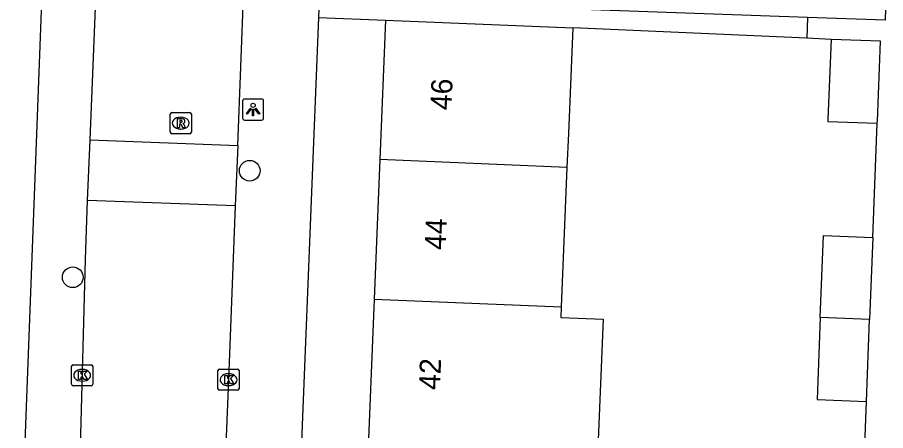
# Model space of a CAD drawing. Extents: x 161355 to 162026, y 386504 to 387459.
# Drawn here: x 161733.14 to 161774.19, y 386889.6 to 386909.14 of the extents above; entities that cross this region are included whole.
import ezdxf

# ---------------------------------------------------------------- set-up
doc = ezdxf.new("R2010")
doc.units = 0
for name, color, linetype in [('IMGEO_Boom', 7, 'Continuous'), ('IMGEO_Kolk', 7, 'Continuous'), ('IMGEO_Lichtpunt', 7, 'Continuous'), ('IMGEO_Pand', 7, 'Continuous'), ('IMGEO_Pand_nummerreeks', 7, 'Continuous'), ('IMGEO_Rijbaan_lokaal_open', 7, 'Continuous'), ('IMGEO_Rioolput', 7, 'Continuous'), ('IMGEO_Voetpad_open', 7, 'Continuous')]:
    doc.layers.add(name, color=color, linetype=linetype)

msp = doc.modelspace()

# ---------------------------------------------------------------- linework, layer by layer
at = {"layer": 'IMGEO_Boom'}
for centre in [(161744.129, 386901.888), (161735.763, 386896.854)]:
    msp.add_circle(centre, 0.489, dxfattribs=at)
at = {"layer": 'IMGEO_Kolk'}
for p, q in [((161735.707, 386891.795), (161735.707, 386892.647)), ((161735.782, 386892.721), (161736.634, 386892.721)), ((161736.195, 386892.501), (161736.22, 386892.501)), ((161736.708, 386892.647), (161736.708, 386891.795)), ((161742.701, 386892.513), (161743.553, 386892.513)), ((161742.626, 386891.587), (161742.626, 386892.439)), ((161743.114, 386892.293), (161743.139, 386892.293)), ((161743.627, 386892.439), (161743.627, 386891.587)), ((161736.634, 386891.721), (161735.782, 386891.721)), ((161736.218, 386891.941), (161736.193, 386891.941)), ((161743.137, 386891.733), (161743.112, 386891.733)), ((161743.553, 386891.513), (161742.701, 386891.513))]:
    msp.add_line(p, q, dxfattribs=at)
for points in [[(161735.707, 386891.795), (161735.707, 386892.647)], [(161735.782, 386892.721), (161736.634, 386892.721)], [(161736.708, 386892.647), (161736.708, 386891.795)], [(161742.701, 386892.513), (161743.553, 386892.513)], [(161736.028, 386892.421), (161736.151, 386892.421), (161736.151, 386892.27), (161736.281, 386892.421), (161736.445, 386892.421), (161736.299, 386892.27), (161736.452, 386892.021), (161736.3, 386892.021), (161736.215, 386892.185), (161736.151, 386892.118), (161736.151, 386892.021), (161736.028, 386892.021), (161736.028, 386892.421)], [(161742.626, 386891.587), (161742.626, 386892.439)], [(161742.947, 386892.213), (161743.07, 386892.213), (161743.07, 386892.062), (161743.2, 386892.213), (161743.364, 386892.213), (161743.218, 386892.062), (161743.371, 386891.813), (161743.219, 386891.813), (161743.134, 386891.977), (161743.07, 386891.91), (161743.07, 386891.813), (161742.947, 386891.813), (161742.947, 386892.213)], [(161743.627, 386892.439), (161743.627, 386891.587)], [(161736.634, 386891.721), (161735.782, 386891.721)], [(161743.553, 386891.513), (161742.701, 386891.513)]]:
    msp.add_lwpolyline(points, dxfattribs=at)
for centre, start, end in [((161735.784, 386892.645), 91.552, 178.448), ((161735.784, 386892.645), 91.552, 178.448), ((161736.632, 386892.645), 1.552, 88.448), ((161736.632, 386892.645), 1.552, 88.448), ((161742.703, 386892.437), 91.552, 178.448), ((161742.703, 386892.437), 91.552, 178.448), ((161743.551, 386892.437), 1.552, 88.448), ((161743.551, 386892.437), 1.552, 88.448), ((161735.784, 386891.797), 181.552, 268.448), ((161735.784, 386891.797), 181.552, 268.448), ((161736.632, 386891.797), 271.552, 358.448), ((161736.632, 386891.797), 271.552, 358.448), ((161742.703, 386891.589), 181.552, 268.448), ((161742.703, 386891.589), 181.552, 268.448), ((161743.551, 386891.589), 271.552, 358.448), ((161743.551, 386891.589), 271.552, 358.448)]:
    msp.add_arc(centre, 0.0765, start, end, dxfattribs=at)
for centre, major_axis, ratio, start_param, end_param in [((161736.194, 386892.221), (-0.387, 0.002), 0.722429, 4.712389, 7.853982), ((161736.219, 386892.221), (-0.39, 0.002), 0.717154, 1.570796, 4.712389), ((161743.113, 386892.013), (-0.387, 0.002), 0.722429, 4.712389, 7.853982), ((161743.138, 386892.013), (-0.39, 0.002), 0.717154, 1.570796, 4.712389)]:
    msp.add_ellipse(centre, major_axis=major_axis, ratio=ratio, start_param=start_param, end_param=end_param, dxfattribs=at)
at = {"layer": 'IMGEO_Lichtpunt'}
for p, q in [((161743.79, 386905.182), (161743.79, 386904.375)), ((161743.79, 386905.182), (161743.79, 386904.375)), ((161744.692, 386905.277), (161743.884, 386905.277)), ((161744.692, 386905.277), (161743.884, 386905.277)), ((161744.786, 386904.375), (161744.786, 386905.182)), ((161744.786, 386904.375), (161744.786, 386905.182)), ((161743.884, 386904.281), (161744.692, 386904.281)), ((161743.884, 386904.281), (161744.692, 386904.281))]:
    msp.add_line(p, q, dxfattribs=at)
for points in [[(161744.164, 386904.846), (161744.203, 386904.818), (161744.015, 386904.556), (161743.977, 386904.583), (161744.164, 386904.846)], [(161744.266, 386904.798), (161744.313, 386904.798), (161744.313, 386904.476), (161744.266, 386904.476), (161744.266, 386904.798)], [(161744.376, 386904.818), (161744.414, 386904.845), (161744.601, 386904.583), (161744.562, 386904.555), (161744.376, 386904.818)]]:
    msp.add_lwpolyline(points, dxfattribs=at)
msp.add_circle((161744.289, 386904.98), 0.0994, dxfattribs=at)
for centre, start, end in [((161743.884, 386905.182), 90, 180), ((161743.884, 386905.182), 90, 180), ((161744.692, 386905.182), 0, 90), ((161744.692, 386905.182), 0, 90), ((161743.884, 386904.375), 180, 270), ((161743.884, 386904.375), 180, 270), ((161744.692, 386904.375), 270, 0), ((161744.692, 386904.375), 270, 360)]:
    msp.add_arc(centre, 0.0946, start, end, dxfattribs=at)
at = {"layer": 'IMGEO_Pand'}
for points in [[(161750.553, 386909.005), (161750.282, 386902.412)], [(161750.553, 386909.005), (161759.396, 386908.642)], [(161759.396, 386908.642), (161759.191, 386903.647), (161759.125, 386902.049)], [(161771.61, 386908.098), (161771.463, 386904.323), (161771.459, 386904.221), (161773.794, 386904.129)], [(161773.794, 386904.129), (161773.8, 386904.231), (161773.947, 386908.006), (161771.61, 386908.098)], [(161750.282, 386902.412), (161750.012, 386895.817)], [(161759.125, 386902.049), (161750.282, 386902.412)], [(161759.125, 386902.049), (161758.855, 386895.454)], [(161771.097, 386894.948), (161771.248, 386898.825), (161773.585, 386898.733)], [(161773.585, 386898.733), (161773.434, 386894.856)], [(161750.012, 386895.817), (161749.741, 386889.221)], [(161750.012, 386895.817), (161758.855, 386895.454)], [(161758.855, 386895.454), (161758.834, 386894.95), (161760.838, 386894.868), (161760.588, 386888.776), (161758.584, 386888.858)], [(161771.097, 386894.948), (161770.945, 386891.071), (161773.283, 386890.979)], [(161773.434, 386894.856), (161771.097, 386894.948)], [(161773.283, 386890.979), (161773.434, 386894.856)]]:
    msp.add_lwpolyline(points, dxfattribs=at)
at = {"layer": 'IMGEO_Rijbaan_lokaal_open'}
for points in [[(161743.573, 386903.075), (161743.848, 386910.54), (161744.562, 386928.116), (161744.774, 386932.351)], [(161736.591, 386903.347), (161736.883, 386910.782), (161737.373, 386923.748), (161737.534, 386927.945), (161737.564, 386928.352), (161737.658, 386929.867)], [(161736.467, 386900.488), (161736.591, 386903.347)], [(161736.591, 386903.347), (161743.573, 386903.075)], [(161743.573, 386903.075), (161743.439, 386900.229)], [(161735.048, 386863.934), (161735.304, 386870.694), (161736.064, 386886.455), (161736.362, 386897.689), (161736.467, 386900.488)], [(161743.439, 386900.229), (161736.467, 386900.488)], [(161743.439, 386900.229), (161743.122, 386892.013), (161742.185, 386868.924), (161741.999, 386863.72)]]:
    msp.add_lwpolyline(points, dxfattribs=at)
at = {"layer": 'IMGEO_Rioolput'}
for p, q in [((161740.368, 386903.713), (161740.368, 386904.565)), ((161740.443, 386904.639), (161741.295, 386904.639)), ((161740.856, 386904.419), (161740.881, 386904.419)), ((161741.369, 386904.565), (161741.369, 386903.713)), ((161741.295, 386903.639), (161740.443, 386903.639)), ((161740.879, 386903.859), (161740.854, 386903.859))]:
    msp.add_line(p, q, dxfattribs=at)
for points in [[(161740.368, 386903.713), (161740.368, 386904.565)], [(161740.443, 386904.639), (161741.295, 386904.639)], [(161741.369, 386904.565), (161741.369, 386903.713)], [(161740.957, 386904.337), (161740.705, 386904.339), (161740.705, 386903.939)], [(161740.705, 386903.939), (161740.829, 386903.939), (161740.829, 386904.101), (161740.84, 386904.101)], [(161740.883, 386904.258), (161740.829, 386904.258), (161740.829, 386904.177)], [(161740.829, 386904.177), (161740.881, 386904.177)], [(161740.887, 386904.072), (161740.958, 386903.939), (161741.098, 386903.939), (161741.033, 386904.065)], [(161741.295, 386903.639), (161740.443, 386903.639)]]:
    msp.add_lwpolyline(points, dxfattribs=at)
for centre, radius, start, end in [((161740.445, 386904.563), 0.0765, 91.552, 178.448), ((161740.445, 386904.563), 0.0765, 91.552, 178.448), ((161741.293, 386904.563), 0.0765, 1.552, 88.448), ((161741.293, 386904.563), 0.0765, 1.552, 88.448), ((161740.839, 386904.048), 0.0533, 26.0293, 88.6989), ((161740.865, 386904.366), 0.19, 274.7715, 282.9687), ((161740.889, 386904.162), 0.0964, 77.0061, 93.1865), ((161740.903, 386904.219), 0.0378, 276.6634, 79.6772), ((161740.956, 386904.227), 0.109, 350.3612, 89.416), ((161740.954, 386904.227), 0.112, 277.5842, 350.9817), ((161740.938, 386904.012), 0.108, 29.5134, 73.7905), ((161740.445, 386903.715), 0.0765, 181.552, 268.448), ((161740.445, 386903.715), 0.0765, 181.552, 268.448), ((161741.293, 386903.715), 0.0765, 271.552, 358.448), ((161741.293, 386903.715), 0.0765, 271.552, 358.448)]:
    msp.add_arc(centre, radius, start, end, dxfattribs=at)
for centre, major_axis, ratio, start_param, end_param in [((161740.855, 386904.139), (-0.387, 0.002), 0.722429, 4.712389, 7.853982), ((161740.88, 386904.139), (-0.39, 0.002), 0.717154, 1.570796, 4.712389)]:
    msp.add_ellipse(centre, major_axis=major_axis, ratio=ratio, start_param=start_param, end_param=end_param, dxfattribs=at)
at = {"layer": 'IMGEO_Voetpad_open'}
for points in [[(161735.088, 386931.106), (161732.284, 386857.44)], [(161747.413, 386909.959), (161747.38, 386909.135)], [(161770.499, 386909.133), (161747.413, 386909.959)], [(161774.189, 386909.561), (161774.165, 386909.002), (161770.499, 386909.133)], [(161747.38, 386909.135), (161744.98, 386849.364)], [(161747.38, 386909.135), (161750.553, 386909.005)], [(161770.499, 386909.133), (161770.466, 386908.149)], [(161770.466, 386908.149), (161759.396, 386908.642)], [(161771.61, 386908.098), (161770.466, 386908.149)], [(161773.585, 386898.733), (161773.794, 386904.129)], [(161773.073, 386885.583), (161773.283, 386890.979)]]:
    msp.add_lwpolyline(points, dxfattribs=at)

# ---------------------------------------------------------------- texts
at = {"layer": 'IMGEO_Pand_nummerreeks'}
for s, rotation, p in [('46', 87.65, (161753.661, 386904.739)), ('44', 87.65, (161753.39, 386898.128)), ('42', 87.6511, (161753.118, 386891.513))]:
    msp.add_text(s, height=1, rotation=rotation, dxfattribs=at).set_placement(p)

doc.saveas('drawing.dxf')
